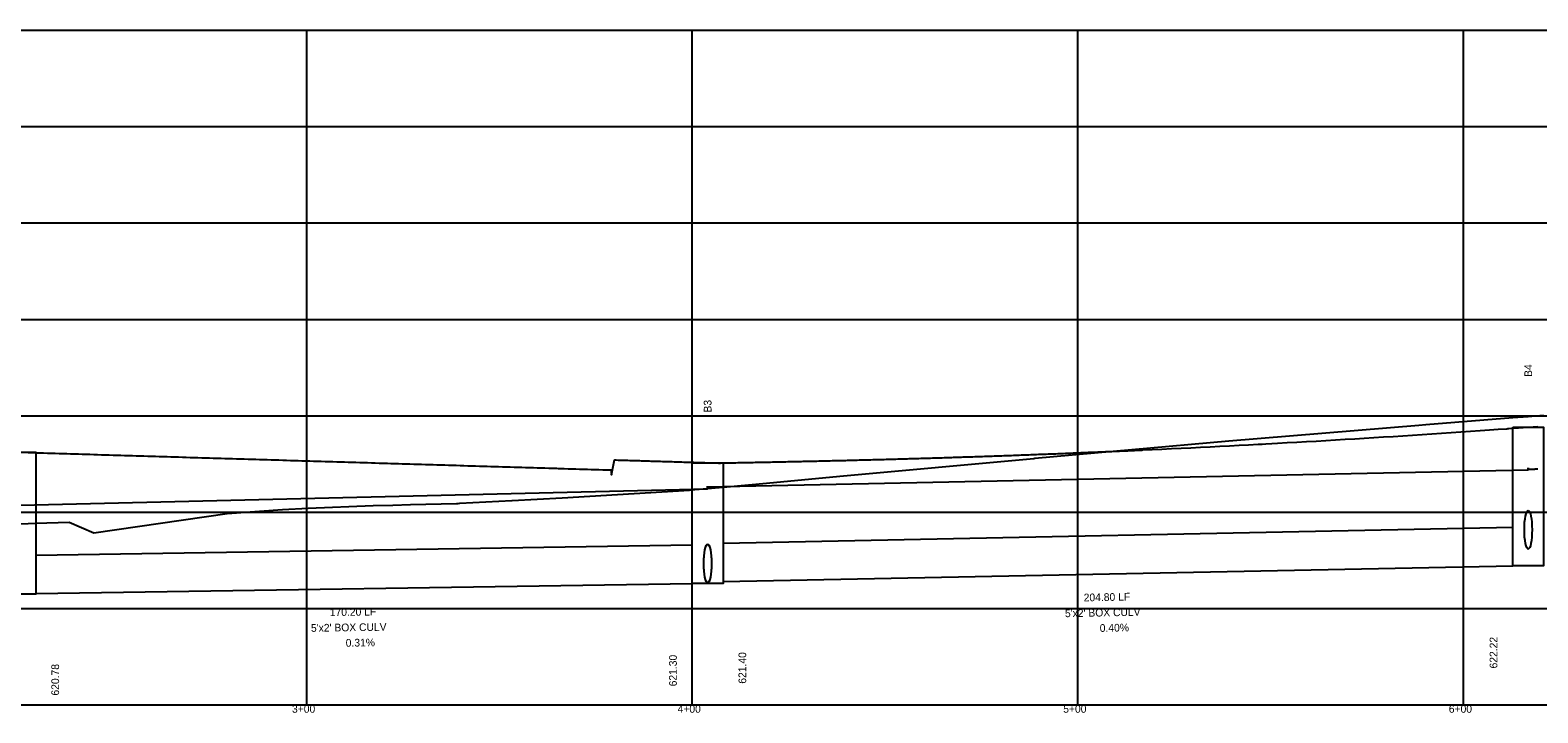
# Model space of a CAD drawing. Extents: x 2254979 to 2278074, y 13790855 to 13792793.
# Drawn here: x 2260189 to 2260580, y 13792139.4 to 13792316.4 of the extents above; entities that cross this region are included whole.
import ezdxf

# ---------------------------------------------------------------- set-up
doc = ezdxf.new("R2010")
doc.units = 0
for name, color, linetype in [('blank4', 7, 'Continuous'), ('D_DRN_PROF_HGL', 7, 'Continuous'), ('D_PROF_1', 7, 'Continuous'), ('D_PROF_NOTES_1', 7, 'Continuous'), ('Default', 7, 'Continuous'), ('Drain_PipeInside', 7, 'Continuous'), ('E_Terrain', 7, 'Continuous'), ('Inlet', 7, 'Continuous'), ('z - Construction', 7, 'Continuous')]:
    doc.layers.add(name, color=color, linetype=linetype)

msp = doc.modelspace()

# ---------------------------------------------------------------- linework, layer by layer
at = {"layer": 'blank4'}
msp.add_lwpolyline([(2259960.69, 13792141.44), (2259960.69, 13792316.44), (2261351.48, 13792316.44), (2261351.48, 13792141.44)], close=True, dxfattribs=at)
at = {"layer": 'D_DRN_PROF_HGL'}
for p, q in [((2260577.47, 13792202.93), (2260577.47, 13792202.61)), ((2260364.67, 13792198.22), (2260364.67, 13792197.98))]:
    msp.add_line(p, q, dxfattribs=at)
for points in [[(2260364.67, 13792197.98), (2260577.47, 13792202.42), (2260577.47, 13792202.93)], [(2260577.47, 13792202.61), (2260577.58, 13792202.61), (2260577.69, 13792202.62), (2260577.8, 13792202.62), (2260577.91, 13792202.62), (2260578.02, 13792202.62), (2260578.13, 13792202.62), (2260578.24, 13792202.63), (2260578.36, 13792202.63), (2260578.47, 13792202.63), (2260578.58, 13792202.63), (2260578.69, 13792202.63), (2260578.8, 13792202.64), (2260578.91, 13792202.64), (2260579.02, 13792202.64), (2260579.13, 13792202.64), (2260579.24, 13792202.65), (2260579.35, 13792202.65), (2260579.46, 13792202.65), (2260579.57, 13792202.65), (2260579.68, 13792202.65), (2260579.79, 13792202.66), (2260579.9, 13792202.66), (2260580.01, 13792202.66)], [(2260186.47, 13792193.28), (2260364.67, 13792197.49), (2260364.67, 13792198.22)]]:
    msp.add_lwpolyline(points, dxfattribs=at)
at = {"layer": 'D_PROF_1'}
msp.add_lwpolyline([(2260188.47, 13792206.93), (2260189.47, 13792206.9), (2260190.47, 13792206.87), (2260190.47, 13792206.87), (2260191.47, 13792206.84), (2260192.47, 13792206.81), (2260193.47, 13792206.78), (2260194.47, 13792206.75), (2260195.47, 13792206.72), (2260196.47, 13792206.69), (2260197.47, 13792206.66), (2260198.47, 13792206.63), (2260199.47, 13792206.6), (2260200.47, 13792206.57), (2260201.32, 13792206.55), (2260201.47, 13792206.54), (2260201.49, 13792206.54), (2260201.52, 13792206.54), (2260202.47, 13792206.51), (2260203.47, 13792206.48), (2260204.47, 13792206.45), (2260205.47, 13792206.42), (2260205.53, 13792206.42), (2260206.47, 13792206.39), (2260207.47, 13792206.36), (2260208.47, 13792206.33), (2260209.47, 13792206.3), (2260210.47, 13792206.27), (2260211.47, 13792206.24), (2260212.47, 13792206.21), (2260213.47, 13792206.18), (2260214.47, 13792206.15), (2260215.47, 13792206.12), (2260216.47, 13792206.09), (2260217.47, 13792206.06), (2260218.47, 13792206.03), (2260219.47, 13792206), (2260220.47, 13792205.97), (2260221.47, 13792205.94), (2260222.47, 13792205.91), (2260223.47, 13792205.88), (2260224.47, 13792205.85), (2260225.47, 13792205.82), (2260226.47, 13792205.79), (2260227.47, 13792205.76), (2260228.47, 13792205.73), (2260229.47, 13792205.7), (2260230.47, 13792205.67), (2260231.47, 13792205.64), (2260232.47, 13792205.61), (2260233.47, 13792205.58), (2260234.47, 13792205.55), (2260235.47, 13792205.52), (2260236.47, 13792205.49), (2260237.47, 13792205.46), (2260238.47, 13792205.43), (2260239.47, 13792205.4), (2260240.47, 13792205.37), (2260241.47, 13792205.34), (2260242.47, 13792205.31), (2260243.47, 13792205.28), (2260244.47, 13792205.25), (2260245.47, 13792205.22), (2260246.47, 13792205.19), (2260247.47, 13792205.16), (2260248.47, 13792205.13), (2260249.47, 13792205.1), (2260250.47, 13792205.07), (2260251.47, 13792205.04), (2260252.47, 13792205.01), (2260253.47, 13792204.98), (2260254.47, 13792204.95), (2260255.47, 13792204.92), (2260256.47, 13792204.89), (2260257.47, 13792204.86), (2260258.47, 13792204.83), (2260259.47, 13792204.8), (2260260.47, 13792204.77), (2260261.47, 13792204.74), (2260262.47, 13792204.71), (2260263.47, 13792204.68), (2260264.47, 13792204.65), (2260265.47, 13792204.62), (2260266.47, 13792204.59), (2260267.47, 13792204.56), (2260268.47, 13792204.53), (2260269.47, 13792204.5), (2260270.47, 13792204.47), (2260271.47, 13792204.44), (2260272.47, 13792204.41), (2260273.47, 13792204.38), (2260274.47, 13792204.35), (2260275.47, 13792204.32), (2260276.47, 13792204.29), (2260277.47, 13792204.26), (2260278.47, 13792204.23), (2260279.47, 13792204.2), (2260280.47, 13792204.17), (2260281.47, 13792204.14), (2260281.68, 13792204.13), (2260282.47, 13792204.11), (2260283.47, 13792204.08), (2260284.47, 13792204.05), (2260285.47, 13792204.02), (2260286.47, 13792203.99), (2260287.47, 13792203.96), (2260288.47, 13792203.93), (2260289.47, 13792203.9), (2260290.47, 13792203.87), (2260291.47, 13792203.84), (2260292.47, 13792203.81), (2260293.47, 13792203.78), (2260294.47, 13792203.75), (2260295.47, 13792203.72), (2260296.47, 13792203.69), (2260297.47, 13792203.66), (2260298.47, 13792203.63), (2260299.47, 13792203.6), (2260300.47, 13792203.57), (2260301.47, 13792203.54), (2260302.47, 13792203.51), (2260303.47, 13792203.48), (2260304.47, 13792203.45), (2260305.47, 13792203.42), (2260306.47, 13792203.39), (2260307.47, 13792203.36), (2260308.47, 13792203.33), (2260309.47, 13792203.3), (2260310.47, 13792203.27), (2260311.47, 13792203.24), (2260312.47, 13792203.21), (2260313.47, 13792203.18), (2260314.47, 13792203.15), (2260315.47, 13792203.12), (2260316.47, 13792203.09), (2260317.47, 13792203.06), (2260318.47, 13792203.03), (2260319.47, 13792203), (2260320.47, 13792202.97), (2260321.47, 13792202.94), (2260322.47, 13792202.91), (2260323.47, 13792202.88), (2260324.47, 13792202.85), (2260325.47, 13792202.82), (2260325.91, 13792202.81), (2260326.47, 13792202.79), (2260327.47, 13792202.76), (2260328.47, 13792202.73), (2260329.47, 13792202.7), (2260330.47, 13792202.67), (2260331.47, 13792202.64), (2260332.47, 13792202.61), (2260333.47, 13792202.58), (2260334.47, 13792202.55), (2260335.47, 13792202.52), (2260336.47, 13792202.49), (2260337.47, 13792202.46), (2260338.47, 13792202.43), (2260339.47, 13792202.4), (2260339.55, 13792202.4), (2260339.75, 13792201.12), (2260340.47, 13792205), (2260340.97, 13792204.99), (2260341.47, 13792204.97), (2260341.97, 13792204.96), (2260342.47, 13792204.94), (2260342.97, 13792204.93), (2260343.47, 13792204.91), (2260343.97, 13792204.9), (2260344.47, 13792204.88), (2260344.97, 13792204.87), (2260345.47, 13792204.85), (2260345.97, 13792204.84), (2260346.47, 13792204.82), (2260346.97, 13792204.81), (2260347.47, 13792204.79), (2260347.97, 13792204.78), (2260348.47, 13792204.76), (2260348.97, 13792204.75), (2260349.47, 13792204.73), (2260349.97, 13792204.72), (2260350.47, 13792204.7), (2260350.97, 13792204.69), (2260351.47, 13792204.67), (2260351.97, 13792204.66), (2260352.47, 13792204.64), (2260352.97, 13792204.63), (2260353.47, 13792204.61), (2260353.97, 13792204.6), (2260354.47, 13792204.58), (2260354.97, 13792204.57), (2260355.47, 13792204.55), (2260355.97, 13792204.54), (2260356.47, 13792204.52), (2260356.97, 13792204.51), (2260357.47, 13792204.49), (2260357.97, 13792204.48), (2260358.47, 13792204.46), (2260358.97, 13792204.45), (2260359.47, 13792204.43), (2260359.97, 13792204.42), (2260360.47, 13792204.4), (2260360.67, 13792204.4), (2260360.67, 13792204.4), (2260360.97, 13792204.39), (2260361.47, 13792204.37), (2260361.97, 13792204.36), (2260362.47, 13792204.34), (2260362.97, 13792204.33), (2260363.47, 13792204.31), (2260363.97, 13792204.3), (2260364.47, 13792204.28), (2260364.67, 13792204.28), (2260364.67, 13792204.28), (2260364.97, 13792204.27), (2260365.47, 13792204.25), (2260365.97, 13792204.24), (2260366.47, 13792204.22), (2260366.97, 13792204.21), (2260367.47, 13792204.19), (2260367.97, 13792204.2), (2260368.47, 13792204.21), (2260368.58, 13792204.22), (2260368.67, 13792204.22), (2260368.67, 13792204.22), (2260368.69, 13792204.22), (2260368.71, 13792204.22), (2260368.73, 13792204.22), (2260369.1, 13792204.23), (2260369.47, 13792204.23), (2260369.97, 13792204.24), (2260370.47, 13792204.25), (2260370.97, 13792204.26), (2260371.47, 13792204.27), (2260371.97, 13792204.28), (2260372.47, 13792204.29), (2260372.97, 13792204.3), (2260373.47, 13792204.31), (2260373.97, 13792204.32), (2260374.47, 13792204.33), (2260374.97, 13792204.34), (2260375.47, 13792204.35), (2260375.97, 13792204.36), (2260376.47, 13792204.37), (2260376.97, 13792204.38), (2260377.47, 13792204.39), (2260377.97, 13792204.4), (2260378.47, 13792204.41), (2260378.97, 13792204.42), (2260379.47, 13792204.43), (2260379.97, 13792204.44), (2260380.47, 13792204.45), (2260380.97, 13792204.46), (2260381.47, 13792204.47), (2260381.97, 13792204.48), (2260382.47, 13792204.49), (2260382.97, 13792204.5), (2260383.47, 13792204.51), (2260383.97, 13792204.52), (2260384.47, 13792204.53), (2260384.97, 13792204.54), (2260385.47, 13792204.55), (2260385.97, 13792204.56), (2260386.47, 13792204.57), (2260386.97, 13792204.58), (2260387.47, 13792204.6), (2260387.97, 13792204.61), (2260388.47, 13792204.62), (2260388.97, 13792204.63), (2260389.47, 13792204.64), (2260389.97, 13792204.65), (2260390.47, 13792204.66), (2260390.97, 13792204.67), (2260391.47, 13792204.68), (2260391.97, 13792204.69), (2260392.47, 13792204.7), (2260392.97, 13792204.71), (2260393.47, 13792204.73), (2260393.97, 13792204.74), (2260394.47, 13792204.75), (2260394.97, 13792204.76), (2260395.47, 13792204.77), (2260395.97, 13792204.78), (2260396.47, 13792204.79), (2260396.97, 13792204.81), (2260397.47, 13792204.82), (2260397.97, 13792204.83), (2260398.47, 13792204.84), (2260398.97, 13792204.85), (2260399.47, 13792204.86), (2260399.97, 13792204.88), (2260400.47, 13792204.89), (2260400.97, 13792204.9), (2260401.47, 13792204.91), (2260401.97, 13792204.93), (2260402.47, 13792204.94), (2260402.97, 13792204.95), (2260403.47, 13792204.96), (2260403.97, 13792204.98), (2260404.47, 13792204.99), (2260404.97, 13792205), (2260405.47, 13792205.01), (2260405.97, 13792205.03), (2260406.47, 13792205.04), (2260406.97, 13792205.05), (2260407.47, 13792205.07), (2260407.97, 13792205.08), (2260408.47, 13792205.09), (2260408.97, 13792205.11), (2260409.47, 13792205.12), (2260409.97, 13792205.13), (2260410.47, 13792205.15), (2260410.97, 13792205.16), (2260411.47, 13792205.17), (2260411.97, 13792205.19), (2260412.47, 13792205.2), (2260412.97, 13792205.22), (2260413.47, 13792205.23), (2260413.97, 13792205.24), (2260414.47, 13792205.26), (2260414.97, 13792205.27), (2260415.47, 13792205.29), (2260415.97, 13792205.3), (2260416.47, 13792205.31), (2260416.97, 13792205.33), (2260417.47, 13792205.34), (2260417.97, 13792205.36), (2260418.47, 13792205.37), (2260418.97, 13792205.39), (2260419.47, 13792205.4), (2260419.97, 13792205.42), (2260420.47, 13792205.43), (2260420.97, 13792205.45), (2260421.47, 13792205.46), (2260421.97, 13792205.48), (2260422.47, 13792205.49), (2260422.97, 13792205.51), (2260423.47, 13792205.52), (2260423.97, 13792205.54), (2260424.47, 13792205.55), (2260424.97, 13792205.57), (2260425.47, 13792205.58), (2260425.97, 13792205.6), (2260426.47, 13792205.62), (2260426.97, 13792205.63), (2260427.47, 13792205.65), (2260427.51, 13792205.65), (2260427.56, 13792205.65), (2260428.01, 13792205.66), (2260428.47, 13792205.68), (2260428.97, 13792205.7), (2260429.47, 13792205.71), (2260429.97, 13792205.73), (2260430.47, 13792205.74), (2260430.97, 13792205.76), (2260431.47, 13792205.78), (2260431.97, 13792205.79), (2260432.47, 13792205.81), (2260432.97, 13792205.83), (2260433.47, 13792205.84), (2260433.97, 13792205.86), (2260434.47, 13792205.88), (2260434.97, 13792205.89), (2260435.47, 13792205.91), (2260435.97, 13792205.93), (2260436.47, 13792205.94), (2260436.97, 13792205.96), (2260437.47, 13792205.98), (2260437.97, 13792206), (2260438.47, 13792206.01), (2260438.97, 13792206.03), (2260439.47, 13792206.05), (2260439.97, 13792206.07), (2260440.47, 13792206.08), (2260440.97, 13792206.1), (2260441.47, 13792206.12), (2260441.97, 13792206.14), (2260442.47, 13792206.15), (2260442.97, 13792206.17), (2260443.47, 13792206.19), (2260443.97, 13792206.21), (2260444.47, 13792206.23), (2260444.97, 13792206.25), (2260445.47, 13792206.26), (2260445.97, 13792206.28), (2260446.47, 13792206.3), (2260446.72, 13792206.31), (2260446.97, 13792206.32), (2260447.22, 13792206.33), (2260447.47, 13792206.34), (2260447.97, 13792206.36), (2260448.47, 13792206.38), (2260448.97, 13792206.39), (2260449.47, 13792206.41), (2260449.97, 13792206.43), (2260450.47, 13792206.45), (2260450.97, 13792206.47), (2260451.47, 13792206.49), (2260451.97, 13792206.51), (2260452.47, 13792206.53), (2260452.97, 13792206.55), (2260453.47, 13792206.57), (2260453.97, 13792206.59), (2260454.47, 13792206.61), (2260454.97, 13792206.62), (2260455.47, 13792206.64), (2260455.97, 13792206.66), (2260456.47, 13792206.68), (2260456.97, 13792206.7), (2260457.47, 13792206.72), (2260457.97, 13792206.74), (2260458.47, 13792206.76), (2260458.97, 13792206.78), (2260459.47, 13792206.8), (2260459.97, 13792206.82), (2260460.47, 13792206.85), (2260460.97, 13792206.87), (2260461.47, 13792206.89), (2260461.97, 13792206.91), (2260462.47, 13792206.93), (2260462.97, 13792206.95), (2260463.47, 13792206.97), (2260463.97, 13792206.99), (2260464.47, 13792207.01), (2260464.97, 13792207.03), (2260465.47, 13792207.05), (2260465.97, 13792207.07), (2260466.47, 13792207.1), (2260466.97, 13792207.12), (2260467.47, 13792207.14), (2260467.97, 13792207.16), (2260468.47, 13792207.18), (2260468.97, 13792207.2), (2260469.47, 13792207.22), (2260469.97, 13792207.25), (2260470.47, 13792207.27), (2260470.97, 13792207.29), (2260471.47, 13792207.31), (2260471.97, 13792207.33), (2260472.47, 13792207.35), (2260472.97, 13792207.38), (2260473.47, 13792207.4), (2260473.6, 13792207.4), (2260473.72, 13792207.41), (2260475.35, 13792207.48), (2260476.99, 13792207.56), (2260477.23, 13792207.57), (2260477.47, 13792207.58), (2260479.97, 13792207.69), (2260482.47, 13792207.81), (2260484.97, 13792207.93), (2260487.47, 13792208.05), (2260489.97, 13792208.17), (2260492.47, 13792208.29), (2260494.97, 13792208.42), (2260497.47, 13792208.54), (2260499.97, 13792208.67), (2260502.47, 13792208.8), (2260504.97, 13792208.93), (2260507.47, 13792209.07), (2260508.47, 13792209.12), (2260509.47, 13792209.17), (2260510.97, 13792209.26), (2260512.47, 13792209.34), (2260514.97, 13792209.48), (2260517.47, 13792209.62), (2260519.97, 13792209.76), (2260522.47, 13792209.9), (2260524.97, 13792210.05), (2260527.47, 13792210.2), (2260529.97, 13792210.35), (2260532.47, 13792210.49), (2260534.97, 13792210.65), (2260537.47, 13792210.8), (2260539.97, 13792210.96), (2260542.47, 13792211.11), (2260544.97, 13792211.27), (2260547.47, 13792211.43), (2260549.97, 13792211.6), (2260552.47, 13792211.76), (2260554.97, 13792211.93), (2260557.47, 13792212.09), (2260559.97, 13792212.26), (2260562.47, 13792212.43), (2260564.97, 13792212.61), (2260567.47, 13792212.78), (2260569.72, 13792212.94), (2260571.97, 13792213.1), (2260572.22, 13792213.12), (2260572.47, 13792213.14), (2260573.47, 13792213.21), (2260573.47, 13792213.21), (2260574.97, 13792213.32), (2260577.47, 13792213.5), (2260577.47, 13792213.5), (2260579.97, 13792213.68)], dxfattribs=at)
at = {"layer": 'Default'}
for p, q in [((2260260.69, 13792141.44), (2260260.69, 13792316.44)), ((2260360.69, 13792141.44), (2260360.69, 13792316.44)), ((2260460.69, 13792141.44), (2260460.69, 13792316.44)), ((2260560.69, 13792141.44), (2260560.69, 13792316.44))]:
    msp.add_line(p, q, dxfattribs=at)
at = {"layer": 'Drain_PipeInside'}
for p, q in [((2260368.67, 13792183.44), (2260573.47, 13792187.54)), ((2260190.47, 13792180.33), (2260360.67, 13792182.94)), ((2260368.67, 13792173.44), (2260573.47, 13792177.54)), ((2260190.47, 13792170.33), (2260360.67, 13792172.94))]:
    msp.add_line(p, q, dxfattribs=at)
for centre in [(2260577.47, 13792186.9), (2260577.47, 13792186.9), (2260364.67, 13792178.18), (2260364.67, 13792178.11)]:
    msp.add_ellipse(centre, major_axis=(0, 5), ratio=0.2, dxfattribs=at)
at = {"layer": 'E_Terrain'}
msp.add_lwpolyline([(2260186.47, 13792188.44), (2260190.47, 13792188.59), (2260190.47, 13792188.59), (2260199.1, 13792188.89), (2260205.46, 13792186.13), (2260240.03, 13792191.1), (2260254.45, 13792192.15), (2260261.03, 13792192.52), (2260277.89, 13792193.15), (2260283.03, 13792193.28), (2260287.64, 13792193.47), (2260299.52, 13792193.69), (2260299.53, 13792193.69), (2260299.54, 13792193.69), (2260299.91, 13792193.7), (2260299.95, 13792193.71), (2260300.01, 13792193.71), (2260300.44, 13792193.8), (2260313.93, 13792194.46), (2260313.96, 13792194.46), (2260326.93, 13792195.17), (2260359.95, 13792197.18), (2260360.67, 13792197.23), (2260360.67, 13792197.23), (2260361.36, 13792197.29), (2260364.67, 13792197.59), (2260364.67, 13792197.59), (2260368.67, 13792197.95), (2260368.67, 13792197.95), (2260379.9, 13792198.97), (2260398.91, 13792200.75), (2260449.24, 13792205.41), (2260449.53, 13792205.43), (2260499.85, 13792209.91), (2260549.1, 13792214.02), (2260550.91, 13792214.16), (2260573.47, 13792215.98), (2260573.47, 13792215.98), (2260577.47, 13792216.3), (2260577.47, 13792216.3), (2260581.47, 13792216.63)], dxfattribs=at)
at = {"layer": 'Inlet'}
for points in [[(2260573.47, 13792213.5), (2260581.47, 13792213.5), (2260581.47, 13792177.54), (2260573.47, 13792177.54)], [(2260182.47, 13792206.99), (2260190.47, 13792206.99), (2260190.47, 13792170.19), (2260182.47, 13792170.19)], [(2260360.67, 13792204.28), (2260368.67, 13792204.28), (2260368.67, 13792172.94), (2260360.67, 13792172.94)]]:
    msp.add_lwpolyline(points, close=True, dxfattribs=at)
at = {"layer": 'z - Construction'}
for p, q in [((2259960.69, 13792291.44), (2261351.48, 13792291.44)), ((2259960.69, 13792266.44), (2261351.48, 13792266.44)), ((2259960.69, 13792241.44), (2261351.48, 13792241.44)), ((2259960.69, 13792216.44), (2261351.48, 13792216.44)), ((2259960.69, 13792191.44), (2261351.48, 13792191.44)), ((2259960.69, 13792166.44), (2261351.48, 13792166.44))]:
    msp.add_line(p, q, dxfattribs=at)

# ---------------------------------------------------------------- texts
at = {"layer": 'D_PROF_NOTES_1'}
for s, rotation, p in [('B4', 90, (2260578.47, 13792226.52)), ('B3', 90, (2260365.67, 13792217.29)), ('204.80 LF', 1.1458, (2260462.21, 13792168.31)), ('170.20 LF', 0.8802, (2260266.69, 13792164.5)), ("5'x2' BOX CULV", 1.1458, (2260457.35, 13792164.22)), ("5'x2' BOX CULV", 0.8802, (2260261.81, 13792160.42)), ('0.40%', 1.1458, (2260466.37, 13792160.4)), ('0.31%', 0.8802, (2260270.82, 13792156.56)), ('622.22', 90, (2260569.47, 13792150.93)), ('621.30', 90, (2260356.67, 13792146.29)), ('621.40', 90, (2260374.67, 13792146.97)), ('620.78', 90, (2260196.47, 13792143.9))]:
    msp.add_text(s, height=2, rotation=rotation, dxfattribs=at).set_placement(p)
at = {"layer": 'Default'}
for s, p in [('3+00', (2260256.88, 13792139.44)), ('4+00', (2260356.88, 13792139.44)), ('5+00', (2260456.88, 13792139.44)), ('6+00', (2260556.88, 13792139.44))]:
    msp.add_text(s, height=2, dxfattribs=at).set_placement(p)

doc.saveas('drawing.dxf')
